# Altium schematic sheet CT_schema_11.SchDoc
size 147 x 119 mm
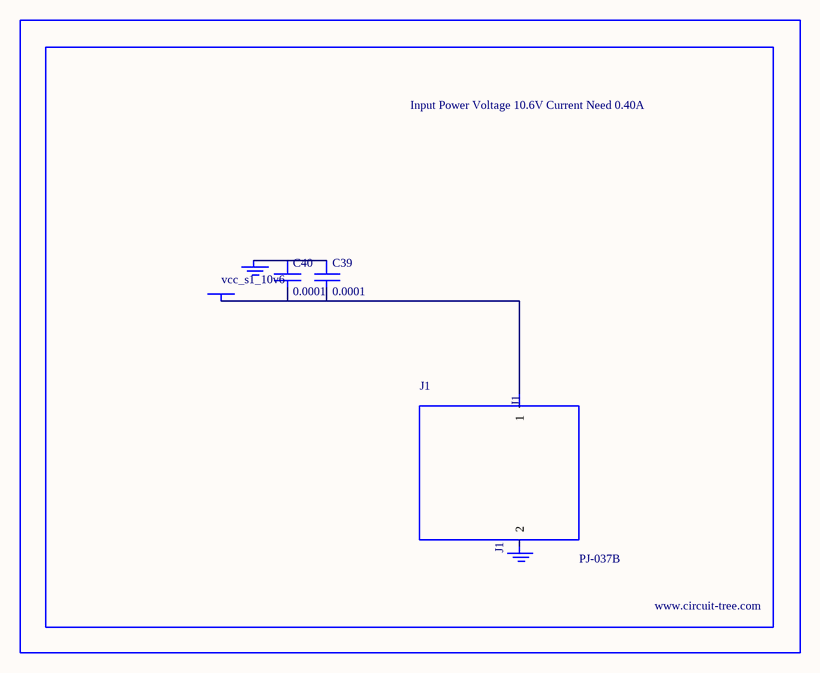
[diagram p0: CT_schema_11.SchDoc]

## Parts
BORDER10  (no value)
C39  0.0001  [EXV-9H]
C40  0.0001  [EXV-9H]
GND_INSTANCE_10_0  (no value)
GND_INSTANCE_10_1  (no value)
J1  PJ-037B  [PJ-037B_PACKAGE]
POWER_INSTANCE_10_0  vcc_s1_10v6

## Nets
NetC39_1: C39.1 C40.1 GND_INSTANCE_10_0.0(GND)
NetC39_2: C39.2 C40.2 J1.1 POWER_INSTANCE_10_0.0(PWR)

Not connected (* = marked no-connect by the designer): GND_INSTANCE_10_1 0(GND); J1 2

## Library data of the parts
BORDER10 = BORDER_PAGE10
C39 C40 = EDK107M035A9HAA
GND_INSTANCE_10_0 GND_INSTANCE_10_1 = GND
POWER_INSTANCE_10_0 = PWR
